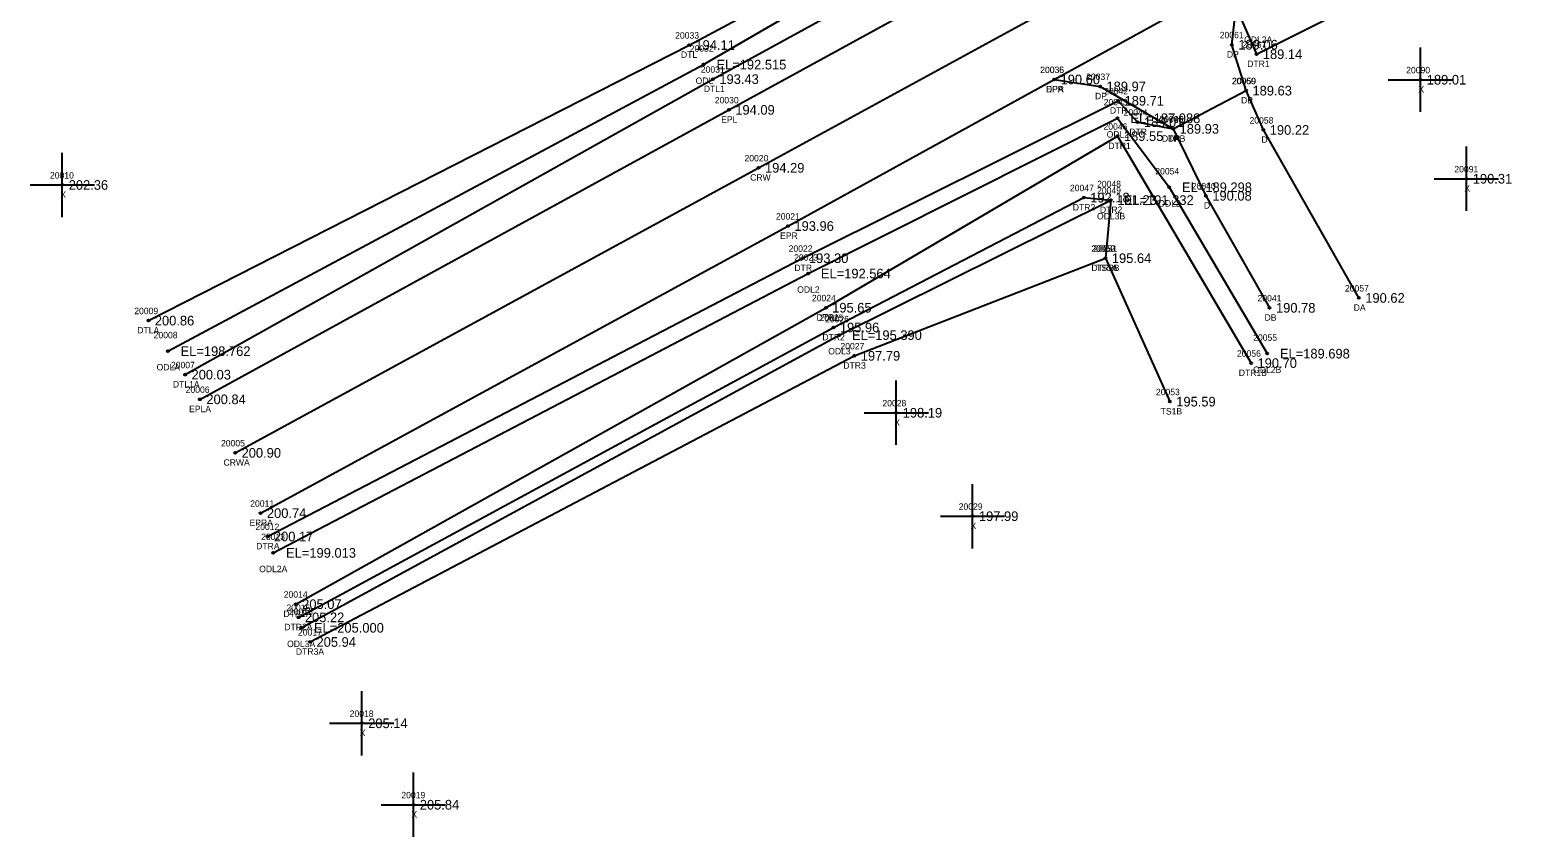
# Model space of a CAD drawing. Extents: x 2279528 to 2280976, y 1061373 to 1062235.
# Drawn here: x 2279527.9 to 2279762.5, y 1061373.4 to 1061498.9 of the extents above; entities that cross this region are included whole.
import ezdxf

# ---------------------------------------------------------------- set-up
doc = ezdxf.new("R2010")
doc.units = 0
for name, color, linetype in [('RD_DTM_BkLn1', 7, 'Continuous'), ('RD_DTM_BkLn2', 7, 'Continuous'), ('RD_DTM_BkLn_txCode', 7, 'Continuous'), ('RD_EX_Driveway', 7, 'Continuous'), ('RD_EX_Driveway_txCode', 7, 'Continuous'), ('RD_EX_H2O', 7, 'Continuous'), ('RD_EX_H2O_txCode', 7, 'Continuous'), ('RD_EX_Misc', 7, 'Continuous'), ('RD_EX_Misc_txCode', 7, 'Continuous'), ('RD_EX_Road', 7, 'Continuous'), ('RD_EX_Road_txCode', 7, 'Continuous'), ('RD_EX_TX_Driveway_ELEV', 7, 'Continuous'), ('RD_EX_TX_H2O_ELEV', 7, 'Continuous'), ('RD_EX_TX_Misc_ELEV', 7, 'Continuous'), ('RD_EX_TX_Road_ELEV', 7, 'Continuous'), ('RD_HC_Survey_ELEV', 7, 'Continuous'), ('RD_HC_Survey_txCode', 7, 'Continuous'), ('RD_SMD_Locator', 7, 'Continuous')]:
    doc.layers.add(name, color=color, linetype=linetype)

msp = doc.modelspace()

# ---------------------------------------------------------------- linework, layer by layer
at = {"layer": 'RD_DTM_BkLn1'}
msp.add_lwpolyline([(2279559.79, 1061433.13), (2279641.23, 1061477.49), (2279727.93, 1061524.84), (2279814.76, 1061571.75), (2279901.26, 1061618.64), (2279982.8, 1061662.56), (2280064.7, 1061706.86), (2280148.08, 1061751.86), (2280234.22, 1061798.46), (2280310.96, 1061840.01), (2280397.69, 1061887.57), (2280487.27, 1061936.5), (2280573.03, 1061983.12), (2280654.64, 1062027.66), (2280741.28, 1062074.45), (2280833.39, 1062123.87), (2280892.52, 1062155.9), (2280939.46, 1062181.85)], dxfattribs=at)
at = {"layer": 'RD_DTM_BkLn2'}
msp.add_line((2279695.2, 1061463.42), (2279705.22, 1061441.1), dxfattribs=at)
at = {"layer": 'RD_EX_Driveway'}
for points in [[(2279687.22, 1061491.24), (2279694.36, 1061490.16), (2279705.74, 1061483.55), (2279717.08, 1061489.5), (2279714.88, 1061496.65), (2279716.07, 1061507.1)], [(2279734.63, 1061457.24), (2279719.77, 1061483.38), (2279717.08, 1061489.5)], [(2279705.74, 1061483.55), (2279710.83, 1061473.14), (2279720.74, 1061455.7)]]:
    msp.add_lwpolyline(points, dxfattribs=at)
at = {"layer": 'RD_EX_H2O'}
for points in [[(2279715.99, 1061501.35), (2279718.69, 1061495.17), (2279737.88, 1061504.81), (2279824.53, 1061553.58), (2279860, 1061573.39)], [(2279546.29, 1061453.71), (2279630.41, 1061496.6), (2279659.08, 1061511.93), (2279655.3, 1061525.45)], [(2279549.3, 1061448.96), (2279632.68, 1061493.55), (2279664.83, 1061512.24), (2279655.3, 1061525.45)], [(2279552, 1061445.3), (2279634.13, 1061491.29), (2279668.82, 1061510.33), (2279666.09, 1061516.71), (2279655.3, 1061525.45)], [(2279564.82, 1061420.11), (2279648.07, 1061463.42), (2279697.17, 1061487.92), (2279700.19, 1061484.6), (2279705.74, 1061483.55)], [(2279565.71, 1061417.56), (2279648.93, 1061461.04), (2279697.09, 1061485.2), (2279705.12, 1061474.46), (2279720.35, 1061448.57)], [(2279569.22, 1061409.58), (2279651.68, 1061455.72), (2279697.08, 1061482.41), (2279717.86, 1061447.1)], [(2279569.64, 1061407.53), (2279652.88, 1061452.64), (2279691.84, 1061472.85), (2279696.06, 1061472.47), (2279695.2, 1061463.42)], [(2279570.05, 1061405.9), (2279653.76, 1061451.45), (2279696.06, 1061472.47)], [(2279571.45, 1061403.7), (2279656.13, 1061448.23), (2279695.2, 1061463.42)]]:
    msp.add_lwpolyline(points, dxfattribs=at)
at = {"layer": 'RD_EX_Misc'}
for p, q in [((2279744.2, 1061486.2), (2279744.2, 1061496.2)), ((2279739.2, 1061491.2), (2279749.2, 1061491.2)), ((2279751.36, 1061470.79), (2279751.36, 1061480.79)), ((2279532.89, 1061469.82), (2279532.89, 1061479.82)), ((2279746.36, 1061475.79), (2279756.36, 1061475.79)), ((2279527.89, 1061474.82), (2279537.89, 1061474.82)), ((2279662.66, 1061434.37), (2279662.66, 1061444.37)), ((2279657.66, 1061439.37), (2279667.66, 1061439.37)), ((2279674.52, 1061418.27), (2279674.52, 1061428.27)), ((2279669.52, 1061423.27), (2279679.52, 1061423.27)), ((2279579.49, 1061386.04), (2279579.49, 1061396.04)), ((2279574.49, 1061391.04), (2279584.49, 1061391.04)), ((2279587.52, 1061373.37), (2279587.52, 1061383.37)), ((2279582.52, 1061378.37), (2279592.52, 1061378.37))]:
    msp.add_line(p, q, dxfattribs=at)
at = {"layer": 'RD_EX_Road'}
for points in [[(2279554.31, 1061441.46), (2279636.61, 1061486.51), (2279673.46, 1061506.76), (2279683.06, 1061512.21), (2279723.14, 1061533.54), (2279809.28, 1061580.29), (2279896.91, 1061627.91), (2279977.07, 1061671.02), (2280059.64, 1061715.57), (2280142.91, 1061760.72), (2280228.83, 1061807.06), (2280306.04, 1061849.18), (2280392.98, 1061896.71), (2280482.82, 1061945.75), (2280567.83, 1061991.78), (2280649.94, 1062036.55), (2280660.56, 1062042.19), (2280676.12, 1062050.66), (2280737.28, 1062083.64), (2280828.54, 1062132.77), (2280887.86, 1062164.61), (2280934.91, 1062190.9)], [(2279563.73, 1061423.75), (2279645.81, 1061468.43), (2279687.22, 1061491.24), (2279716.07, 1061507.1), (2279732.53, 1061515.67), (2279819.45, 1061563.03), (2279856.79, 1061583.22), (2279872.52, 1061591.57), (2279906, 1061609.76), (2279987.33, 1061653.65)]]:
    msp.add_lwpolyline(points, dxfattribs=at)
at = {"layer": 'RD_SMD_Locator'}
for centre in [(2279630.41, 1061496.6), (2279714.88, 1061496.65), (2279718.69, 1061495.17), (2279632.68, 1061493.55), (2279634.13, 1061491.29), (2279687.22, 1061491.24), (2279687.22, 1061491.24), (2279694.36, 1061490.16), (2279717.08, 1061489.5), (2279717.08, 1061489.5), (2279744.2, 1061491.2), (2279697.17, 1061487.92), (2279636.61, 1061486.51), (2279697.09, 1061485.2), (2279700.19, 1061484.6), (2279705.74, 1061483.55), (2279705.74, 1061483.55), (2279705.74, 1061483.55), (2279719.77, 1061483.38), (2279697.08, 1061482.41), (2279641.23, 1061477.49), (2279751.36, 1061475.79), (2279532.89, 1061474.82), (2279705.12, 1061474.46), (2279710.83, 1061473.14), (2279691.84, 1061472.85), (2279696.06, 1061472.47), (2279696.06, 1061472.47), (2279645.81, 1061468.43), (2279648.07, 1061463.42), (2279695.2, 1061463.42), (2279695.2, 1061463.42), (2279695.2, 1061463.42), (2279648.93, 1061461.04), (2279734.63, 1061457.24), (2279651.68, 1061455.72), (2279720.74, 1061455.7), (2279546.29, 1061453.71), (2279652.88, 1061452.64), (2279653.76, 1061451.45), (2279549.3, 1061448.96), (2279656.13, 1061448.23), (2279720.35, 1061448.57), (2279552, 1061445.3), (2279717.86, 1061447.1), (2279554.31, 1061441.46), (2279705.22, 1061441.1), (2279662.66, 1061439.37), (2279559.79, 1061433.13), (2279563.73, 1061423.75), (2279674.52, 1061423.27), (2279564.82, 1061420.11), (2279565.71, 1061417.56), (2279569.22, 1061409.58), (2279569.64, 1061407.53), (2279570.05, 1061405.9), (2279571.45, 1061403.7), (2279579.49, 1061391.04), (2279587.52, 1061378.37)]:
    msp.add_circle(centre, 0.15, dxfattribs=at)

# ---------------------------------------------------------------- texts
at = {"layer": 'RD_DTM_BkLn_txCode'}
for s, p in [('20052', (2279693.04, 1061464.42)), ('TS1A', (2279693.75, 1061461.42)), ('20053', (2279703.06, 1061442.1)), ('TS1B', (2279703.79, 1061439.1))]:
    msp.add_text(s, height=1, dxfattribs=at).set_placement(p)
at = {"layer": 'RD_EX_Driveway_txCode'}
for s, p in [('20061', (2279712.99, 1061497.65)), ('DP', (2279714.1, 1061494.65)), ('20036', (2279685.04, 1061492.24)), ('20037', (2279692.2, 1061491.16)), ('DPA', (2279685.95, 1061489.24)), ('20060', (2279714.86, 1061490.5)), ('20059', (2279714.93, 1061490.5)), ('DP', (2279693.58, 1061488.16)), ('DB', (2279716.3, 1061487.5)), ('DP', (2279716.3, 1061487.5)), ('20038', (2279703.59, 1061484.55)), ('20039', (2279703.59, 1061484.55)), ('20058', (2279717.62, 1061484.38)), ('DA', (2279704.95, 1061481.55)), ('DP', (2279704.96, 1061481.55)), ('D', (2279719.47, 1061481.38)), ('20040', (2279708.64, 1061474.14)), ('D', (2279710.53, 1061471.14)), ('20057', (2279732.47, 1061458.24)), ('20041', (2279718.87, 1061456.7)), ('DB', (2279719.96, 1061453.7)), ('DA', (2279733.83, 1061455.24))]:
    msp.add_text(s, height=1, dxfattribs=at).set_placement(p)
at = {"layer": 'RD_EX_H2O_txCode'}
for s, p in [('20033', (2279628.25, 1061497.6)), ('20067', (2279716.51, 1061496.17)), ('ODL2A', (2279716.78, 1061496.94)), ('DTL', (2279629.16, 1061494.6)), ('20032', (2279630.52, 1061495.55)), ('20031', (2279632.25, 1061492.29)), ('DTR1', (2279717.26, 1061493.17)), ('ODL', (2279631.43, 1061490.55)), ('DTL1', (2279632.72, 1061489.29)), ('20042', (2279695.01, 1061488.92)), ('20043', (2279694.93, 1061487.2)), ('DTR', (2279695.9, 1061485.92)), ('20044', (2279698.03, 1061485.6)), ('20045', (2279703.59, 1061484.55)), ('20046', (2279694.9, 1061483.41)), ('ODL2', (2279695.4, 1061482.2)), ('DTR', (2279698.92, 1061482.6)), ('DTR1', (2279695.65, 1061480.41)), ('DTRB', (2279704, 1061481.55)), ('20054', (2279702.96, 1061476.46)), ('20047', (2279689.68, 1061473.85)), ('20048', (2279693.9, 1061474.47)), ('20049', (2279693.9, 1061473.47)), ('DTR2', (2279690.12, 1061470.85)), ('DTR2', (2279694.34, 1061470.47)), ('ODL2', (2279703.42, 1061471.46)), ('ODL3B', (2279693.89, 1061469.47)), ('20022', (2279645.91, 1061464.42)), ('20023', (2279646.77, 1061463.04)), ('20050', (2279693, 1061464.42)), ('20051', (2279693.33, 1061464.42)), ('DTR', (2279646.8, 1061461.42)), ('DTR2B', (2279693.01, 1061461.42)), ('DTR3B', (2279693.01, 1061461.42)), ('ODL2', (2279647.24, 1061458.04)), ('20024', (2279649.53, 1061456.72)), ('20009', (2279544.09, 1061454.71)), ('DTR1', (2279650.25, 1061453.72)), ('20025', (2279650.72, 1061453.64)), ('20026', (2279651.58, 1061453.45)), ('DTLA', (2279544.56, 1061451.71)), ('20008', (2279547.11, 1061450.96)), ('DTR2', (2279651.16, 1061450.64)), ('20027', (2279653.97, 1061449.23)), ('20055', (2279718.19, 1061450.57)), ('ODL3', (2279652.07, 1061448.45)), ('20056', (2279715.67, 1061448.1)), ('ODLA', (2279547.57, 1061445.96)), ('20007', (2279549.8, 1061446.3)), ('DTR3', (2279654.42, 1061446.23)), ('DTR1B', (2279715.95, 1061445.1)), ('ODL2B', (2279718.18, 1061445.57)), ('DTL1A', (2279550.1, 1061443.3)), ('20012', (2279562.94, 1061421.11)), ('20013', (2279563.83, 1061419.56)), ('DTRA', (2279563.06, 1061418.11)), ('ODL2A', (2279563.53, 1061414.56)), ('20014', (2279567.35, 1061410.58)), ('DTR1A', (2279567.3, 1061407.58)), ('20015', (2279567.77, 1061408.53)), ('20016', (2279568.16, 1061407.9)), ('DTR2A', (2279567.44, 1061405.53)), ('20017', (2279569.57, 1061404.7)), ('ODL3A', (2279567.87, 1061402.9)), ('DTR3A', (2279569.24, 1061401.7))]:
    msp.add_text(s, height=1, dxfattribs=at).set_placement(p)
at = {"layer": 'RD_EX_Misc_txCode'}
for s, p in [('20090', (2279742, 1061492.2)), ('X', (2279743.89, 1061489.2)), ('20010', (2279530.98, 1061475.82)), ('20091', (2279749.49, 1061476.79)), ('X', (2279532.58, 1061472.82)), ('X', (2279751.05, 1061473.79)), ('20028', (2279660.5, 1061440.37)), ('X', (2279662.34, 1061437.37)), ('20029', (2279672.37, 1061424.27)), ('X', (2279674.21, 1061421.27)), ('20018', (2279577.61, 1061392.04)), ('X', (2279579.17, 1061389.04)), ('20019', (2279585.65, 1061379.37)), ('X', (2279587.21, 1061376.37))]:
    msp.add_text(s, height=1, dxfattribs=at).set_placement(p)
at = {"layer": 'RD_EX_Road_txCode'}
for s, p in [('20035', (2279685.06, 1061492.24)), ('EPR', (2279685.99, 1061489.24)), ('20030', (2279634.42, 1061487.51)), ('EPL', (2279635.41, 1061484.51)), ('20021', (2279643.94, 1061469.43)), ('EPR', (2279644.58, 1061466.43)), ('20006', (2279552.09, 1061442.46)), ('EPLA', (2279552.62, 1061439.46)), ('20011', (2279562.14, 1061424.75)), ('EPRA', (2279562.02, 1061421.75))]:
    msp.add_text(s, height=1, dxfattribs=at).set_placement(p)
at = {"layer": 'RD_EX_TX_Driveway_ELEV'}
for s, p in [('189.06', (2279715.88, 1061495.9)), ('190.60', (2279688.22, 1061490.49)), ('189.97', (2279695.36, 1061489.41)), ('189.63', (2279718.08, 1061488.75)), ('189.63', (2279718.08, 1061488.75)), ('189.93', (2279706.74, 1061482.8)), ('189.93', (2279706.74, 1061482.8)), ('190.22', (2279720.77, 1061482.63)), ('190.08', (2279711.83, 1061472.39)), ('190.62', (2279735.63, 1061456.49)), ('190.78', (2279721.74, 1061454.95))]:
    msp.add_text(s, height=1.5, dxfattribs=at).set_placement(p)
at = {"layer": 'RD_EX_TX_H2O_ELEV'}
for s, p in [('194.11', (2279631.41, 1061495.85)), ('EL=192.515', (2279634.68, 1061492.8)), ('189.14', (2279719.69, 1061494.42)), ('193.43', (2279635.13, 1061490.54)), ('189.71', (2279698.17, 1061487.17)), ('EL=187.988', (2279699.09, 1061484.45)), ('189.01', (2279701.19, 1061483.85)), ('189.55', (2279698.08, 1061481.66)), ('189.93', (2279706.74, 1061482.8)), ('192.18', (2279692.84, 1061472.1)), ('191.23', (2279697.06, 1061471.72)), ('EL=191.232', (2279698.06, 1061471.72)), ('EL=189.298', (2279707.12, 1061473.71)), ('193.30', (2279649.07, 1061462.67)), ('195.64', (2279696.2, 1061462.67)), ('195.64', (2279696.2, 1061462.67)), ('EL=192.564', (2279650.93, 1061460.29)), ('200.86', (2279547.29, 1061452.96)), ('195.65', (2279652.68, 1061454.97)), ('195.96', (2279653.88, 1061451.89)), ('EL=195.390', (2279655.76, 1061450.7)), ('EL=198.762', (2279551.3, 1061448.21)), ('197.79', (2279657.13, 1061447.48)), ('190.70', (2279718.86, 1061446.35)), ('EL=189.698', (2279722.35, 1061447.82)), ('200.03', (2279553, 1061444.55)), ('200.17', (2279565.82, 1061419.36)), ('EL=199.013', (2279567.71, 1061416.81)), ('205.07', (2279570.22, 1061408.83)), ('205.22', (2279570.64, 1061406.78)), ('EL=205.000', (2279572.05, 1061405.15)), ('205.94', (2279572.45, 1061402.95))]:
    msp.add_text(s, height=1.5, dxfattribs=at).set_placement(p)
at = {"layer": 'RD_EX_TX_Misc_ELEV'}
for s, p in [('189.01', (2279745.2, 1061490.45)), ('202.36', (2279533.89, 1061474.07)), ('190.31', (2279752.36, 1061475.04)), ('195.64', (2279696.2, 1061462.67)), ('195.59', (2279706.22, 1061440.35)), ('198.19', (2279663.66, 1061438.62)), ('197.99', (2279675.52, 1061422.52)), ('205.14', (2279580.49, 1061390.29)), ('205.84', (2279588.52, 1061377.62))]:
    msp.add_text(s, height=1.5, dxfattribs=at).set_placement(p)
at = {"layer": 'RD_EX_TX_Road_ELEV'}
for s, p in [('190.60', (2279688.22, 1061490.49)), ('194.09', (2279637.61, 1061485.76)), ('193.96', (2279646.81, 1061467.68)), ('200.84', (2279555.31, 1061440.71)), ('200.74', (2279564.73, 1061423))]:
    msp.add_text(s, height=1.5, dxfattribs=at).set_placement(p)
at = {"layer": 'RD_HC_Survey_ELEV'}
for s, p in [('194.29', (2279642.23, 1061476.74)), ('200.90', (2279560.79, 1061432.38))]:
    msp.add_text(s, height=1.5, dxfattribs=at).set_placement(p)
at = {"layer": 'RD_HC_Survey_txCode'}
for s, p in [('20020', (2279639.04, 1061478.49)), ('CRW', (2279639.92, 1061475.49)), ('20005', (2279557.59, 1061434.13)), ('CRWA', (2279557.98, 1061431.13))]:
    msp.add_text(s, height=1, dxfattribs=at).set_placement(p)

doc.saveas('drawing.dxf')
